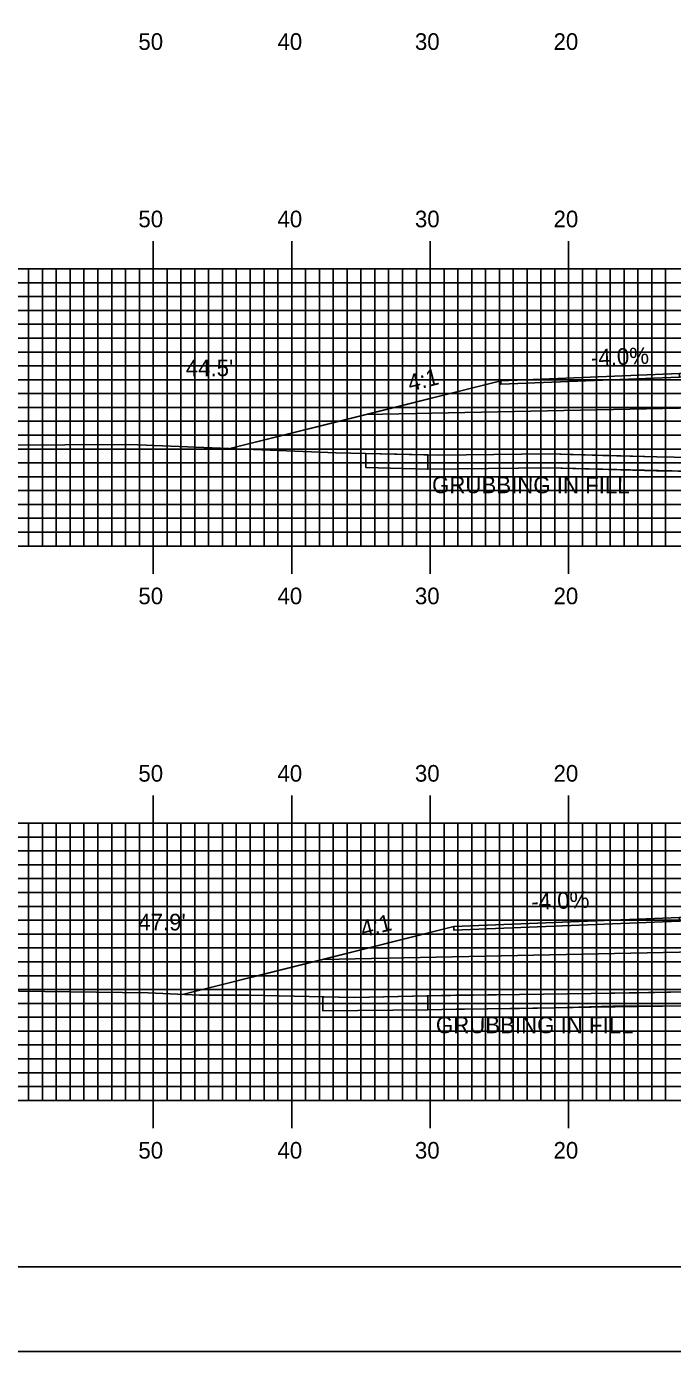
# Model space of a CAD drawing. Extents: x 1773990 to 1774333, y 442591 to 442811.
# Drawn here: x 1774096.5 to 1774143.2, y 442590.5 to 442686.2 of the extents above; entities that cross this region are included whole.
import ezdxf

# ---------------------------------------------------------------- set-up
doc = ezdxf.new("R2010")
doc.units = 0
for name, color, linetype in [('ANNOTATION', 7, 'Continuous'), ('BORDER', 7, 'Continuous'), ('D_Roadway_Centerline', 7, 'Continuous'), ('D_Roadway_Edge_Shoulder', 7, 'Continuous'), ('D_Roadway_SlopeLines', 7, 'Continuous'), ('D_Roadway_SubGrade', 7, 'Continuous'), ('D_Text_Standard', 7, 'Continuous'), ('GRUBBING IN FILL', 7, 'Continuous'), ('H_V ANNOTATION', 7, 'Continuous'), ('MAJOR', 7, 'Continuous'), ('MINOR', 7, 'Continuous'), ('PLOT BOUNDARY', 7, 'Continuous'), ('S_Roadway_Centerline', 7, 'Continuous')]:
    doc.layers.add(name, color=color, linetype=linetype)

msp = doc.modelspace()

# ---------------------------------------------------------------- linework, layer by layer
at = {"layer": 'BORDER'}
msp.add_lwpolyline([(1774006.059, 442596.665), (1774326.059, 442596.665), (1774326.059, 442806.665), (1774006.059, 442806.665)], close=True, dxfattribs=at)
at = {"layer": 'D_Roadway_Centerline'}
for points in [[(1774111.186, 442655.695), (1774121.01, 442658.151), (1774130.759, 442660.588), (1774143.659, 442661.104), (1774143.66, 442661.104), (1774152.062, 442661.272), (1774155.659, 442661.344), (1774167.659, 442661.104), (1774170.226, 442661.002), (1774175.659, 442660.784), (1774184.924, 442658.468), (1774185.833, 442658.24), (1774201.809, 442654.246), (1774201.81, 442654.246)], [(1774107.784, 442616.308), (1774117.905, 442618.838), (1774127.359, 442621.202), (1774143.659, 442621.854), (1774155.659, 442622.094), (1774161.174, 442621.984), (1774167.659, 442621.854), (1774171.953, 442621.682), (1774175.659, 442621.534), (1774185.833, 442618.99), (1774199.367, 442615.606)]]:
    msp.add_lwpolyline(points, dxfattribs=at)
at = {"layer": 'D_Roadway_Edge_Shoulder'}
for points in [[(1774143.659, 442661.104), (1774130.759, 442660.588), (1774130.759, 442660.338), (1774143.659, 442660.854)], [(1774143.659, 442621.854), (1774127.359, 442621.202), (1774127.359, 442620.952), (1774143.659, 442621.604)]]:
    msp.add_lwpolyline(points, close=True, dxfattribs=at)
at = {"layer": 'D_Roadway_SlopeLines'}
for points in [[(1774130.759, 442660.588), (1774120.585, 442658.044), (1774118.76, 442657.588), (1774111.186, 442655.695)], [(1774127.359, 442621.202), (1774117.185, 442618.658), (1774115.358, 442618.202), (1774107.784, 442616.308)]]:
    msp.add_lwpolyline(points, dxfattribs=at)
at = {"layer": 'D_Roadway_SubGrade'}
for points in [[(1774143.659, 442658.604), (1774121.01, 442658.151), (1774130.759, 442660.588), (1774130.759, 442660.338), (1774143.659, 442660.854), (1774155.659, 442661.094), (1774167.659, 442660.854), (1774175.659, 442660.534), (1774175.659, 442660.784), (1774185.833, 442658.24), (1774167.659, 442658.604), (1774155.659, 442658.844)], [(1774143.659, 442619.354), (1774117.905, 442618.838), (1774127.359, 442621.202), (1774127.359, 442620.952), (1774143.659, 442621.604), (1774155.659, 442621.844), (1774167.659, 442621.604), (1774175.659, 442621.284), (1774175.659, 442621.534), (1774185.833, 442618.99), (1774167.659, 442619.354), (1774155.659, 442619.594)]]:
    msp.add_lwpolyline(points, close=True, dxfattribs=at)
at = {"layer": 'GRUBBING IN FILL'}
for p, q in [((1774125.485, 442655.237), (1774121.01, 442655.333)), ((1774125.485, 442655.237), (1774125.485, 442654.211)), ((1774125.485, 442654.211), (1774125.485, 442655.237)), ((1774120.185, 442616.092), (1774117.905, 442616.138)), ((1774125.485, 442616.21), (1774120.185, 442616.092)), ((1774125.485, 442616.21), (1774125.485, 442615.21)), ((1774125.485, 442615.21), (1774125.485, 442616.21))]:
    msp.add_line(p, q, dxfattribs=at)
for points in [[(1774121.01, 442655.333), (1774121.01, 442654.333), (1774125.485, 442654.211)], [(1774121.01, 442655.333), (1774121.01, 442654.333), (1774125.485, 442654.211)], [(1774125.485, 442654.211), (1774134.235, 442654.315), (1774138.123, 442654.206), (1774145.135, 442654.046), (1774148.26, 442653.994), (1774152.504, 442653.952), (1774155.659, 442653.921), (1774155.659, 442654.921), (1774152.509, 442654.952), (1774148.273, 442654.994), (1774142.032, 442655.097), (1774138.138, 442655.206), (1774134.243, 442655.315), (1774130.25, 442655.268), (1774126.257, 442655.22), (1774125.485, 442655.237)], [(1774125.485, 442654.211), (1774134.235, 442654.315), (1774142.01, 442654.097), (1774148.26, 442653.994), (1774156.748, 442653.91), (1774168.548, 442654.069), (1774170.602, 442654.088), (1774172.142, 442654.082), (1774185.833, 442653.644)], [(1774125.485, 442654.211), (1774134.235, 442654.315), (1774142.01, 442654.097), (1774148.26, 442653.994), (1774156.748, 442653.91), (1774168.548, 442654.069), (1774170.602, 442654.088), (1774172.142, 442654.082), (1774185.833, 442653.644)], [(1774125.485, 442616.21), (1774132.101, 442616.307), (1774140.725, 442616.436), (1774144.174, 442616.491), (1774150.849, 442616.51), (1774155.659, 442616.523), (1774155.659, 442615.522), (1774150.852, 442615.51), (1774147.518, 442615.5), (1774144.183, 442615.491), (1774138.846, 442615.476), (1774134.703, 442615.344), (1774126.507, 442615.233), (1774125.485, 442615.21)], [(1774117.905, 442616.138), (1774117.905, 442615.138), (1774125.485, 442615.21)], [(1774117.905, 442616.138), (1774117.905, 442615.138), (1774125.485, 442615.21)], [(1774125.485, 442615.21), (1774127.529, 442615.255), (1774132.114, 442615.307), (1774137.292, 442615.382), (1774144.183, 442615.491), (1774150.852, 442615.51), (1774155.673, 442615.522), (1774160.779, 442615.365), (1774178.086, 442614.715), (1774185.833, 442614.569)], [(1774125.485, 442615.21), (1774127.529, 442615.255), (1774132.114, 442615.307), (1774137.292, 442615.382), (1774144.183, 442615.491), (1774150.852, 442615.51), (1774155.673, 442615.522), (1774160.779, 442615.365), (1774178.086, 442614.715), (1774185.833, 442614.569)]]:
    msp.add_lwpolyline(points, dxfattribs=at)
for points in [[(1774125.485, 442655.237), (1774125.485, 442654.211), (1774134.235, 442654.315), (1774138.123, 442654.206), (1774145.135, 442654.046), (1774148.26, 442653.994), (1774152.504, 442653.952), (1774155.659, 442653.921), (1774155.659, 442654.921), (1774152.509, 442654.952), (1774148.273, 442654.994), (1774142.032, 442655.097), (1774138.138, 442655.206), (1774134.243, 442655.315), (1774130.25, 442655.268), (1774126.257, 442655.22)], [(1774125.485, 442616.21), (1774132.101, 442616.307), (1774140.725, 442616.436), (1774144.174, 442616.491), (1774150.849, 442616.51), (1774155.659, 442616.523), (1774155.659, 442615.522), (1774150.852, 442615.51), (1774147.518, 442615.5), (1774144.183, 442615.491), (1774138.846, 442615.476), (1774134.703, 442615.344), (1774126.507, 442615.233), (1774125.485, 442615.21)]]:
    msp.add_lwpolyline(points, close=True, dxfattribs=at)
at = {"layer": 'MAJOR'}
for p, q in [((1774105.659, 442670.669), (1774105.659, 442668.665)), ((1774115.659, 442670.669), (1774115.659, 442668.665)), ((1774125.659, 442670.669), (1774125.659, 442668.665)), ((1774135.659, 442670.669), (1774135.659, 442668.665)), ((1774015.659, 442668.665), (1774295.659, 442668.665)), ((1774015.659, 442668.665), (1774295.659, 442668.665)), ((1774105.659, 442648.665), (1774105.659, 442668.665)), ((1774115.659, 442648.665), (1774115.659, 442668.665)), ((1774125.659, 442648.665), (1774125.659, 442668.665)), ((1774135.659, 442648.665), (1774135.659, 442668.665)), ((1774015.659, 442663.665), (1774295.659, 442663.665)), ((1774015.659, 442658.665), (1774295.659, 442658.665)), ((1774015.659, 442653.665), (1774295.659, 442653.665)), ((1774015.659, 442648.665), (1774295.659, 442648.665)), ((1774015.659, 442648.665), (1774295.659, 442648.665)), ((1774105.659, 442646.661), (1774105.659, 442648.665)), ((1774115.659, 442646.661), (1774115.659, 442648.665)), ((1774125.659, 442646.661), (1774125.659, 442648.665)), ((1774135.659, 442646.661), (1774135.659, 442648.665)), ((1774105.659, 442630.669), (1774105.659, 442628.665)), ((1774115.659, 442630.669), (1774115.659, 442628.665)), ((1774125.659, 442630.669), (1774125.659, 442628.665)), ((1774135.659, 442630.669), (1774135.659, 442628.665)), ((1774015.659, 442628.665), (1774295.659, 442628.665)), ((1774015.659, 442628.665), (1774295.659, 442628.665)), ((1774105.659, 442608.665), (1774105.659, 442628.665)), ((1774115.659, 442608.665), (1774115.659, 442628.665)), ((1774125.659, 442608.665), (1774125.659, 442628.665)), ((1774135.659, 442608.665), (1774135.659, 442628.665)), ((1774015.659, 442623.665), (1774295.659, 442623.665)), ((1774015.659, 442618.665), (1774295.659, 442618.665)), ((1774015.659, 442613.665), (1774295.659, 442613.665)), ((1774015.659, 442608.665), (1774295.659, 442608.665)), ((1774015.659, 442608.665), (1774295.659, 442608.665)), ((1774105.659, 442606.661), (1774105.659, 442608.665)), ((1774115.659, 442606.661), (1774115.659, 442608.665)), ((1774125.659, 442606.661), (1774125.659, 442608.665)), ((1774135.659, 442606.661), (1774135.659, 442608.665))]:
    msp.add_line(p, q, dxfattribs=at)
at = {"layer": 'MINOR'}
for p, q in [((1774096.659, 442648.665), (1774096.659, 442668.665)), ((1774097.659, 442648.665), (1774097.659, 442668.665)), ((1774098.659, 442648.665), (1774098.659, 442668.665)), ((1774099.659, 442648.665), (1774099.659, 442668.665)), ((1774100.659, 442648.665), (1774100.659, 442668.665)), ((1774101.659, 442648.665), (1774101.659, 442668.665)), ((1774102.659, 442648.665), (1774102.659, 442668.665)), ((1774103.659, 442648.665), (1774103.659, 442668.665)), ((1774104.659, 442648.665), (1774104.659, 442668.665)), ((1774106.659, 442648.665), (1774106.659, 442668.665)), ((1774107.659, 442648.665), (1774107.659, 442668.665)), ((1774108.659, 442648.665), (1774108.659, 442668.665)), ((1774109.659, 442648.665), (1774109.659, 442668.665)), ((1774110.659, 442648.665), (1774110.659, 442668.665)), ((1774111.659, 442648.665), (1774111.659, 442668.665)), ((1774112.659, 442648.665), (1774112.659, 442668.665)), ((1774113.659, 442648.665), (1774113.659, 442668.665)), ((1774114.659, 442648.665), (1774114.659, 442668.665)), ((1774116.659, 442648.665), (1774116.659, 442668.665)), ((1774117.659, 442648.665), (1774117.659, 442668.665)), ((1774118.659, 442648.665), (1774118.659, 442668.665)), ((1774119.659, 442648.665), (1774119.659, 442668.665)), ((1774120.659, 442648.665), (1774120.659, 442668.665)), ((1774121.659, 442648.665), (1774121.659, 442668.665)), ((1774122.659, 442648.665), (1774122.659, 442668.665)), ((1774123.659, 442648.665), (1774123.659, 442668.665)), ((1774124.659, 442648.665), (1774124.659, 442668.665)), ((1774126.659, 442648.665), (1774126.659, 442668.665)), ((1774127.659, 442648.665), (1774127.659, 442668.665)), ((1774128.659, 442648.665), (1774128.659, 442668.665)), ((1774129.659, 442648.665), (1774129.659, 442668.665)), ((1774130.659, 442648.665), (1774130.659, 442668.665)), ((1774131.659, 442648.665), (1774131.659, 442668.665)), ((1774132.659, 442648.665), (1774132.659, 442668.665)), ((1774133.659, 442648.665), (1774133.659, 442668.665)), ((1774134.659, 442648.665), (1774134.659, 442668.665)), ((1774136.659, 442648.665), (1774136.659, 442668.665)), ((1774137.659, 442648.665), (1774137.659, 442668.665)), ((1774138.659, 442648.665), (1774138.659, 442668.665)), ((1774139.659, 442648.665), (1774139.659, 442668.665)), ((1774140.659, 442648.665), (1774140.659, 442668.665)), ((1774141.659, 442648.665), (1774141.659, 442668.665)), ((1774142.659, 442648.665), (1774142.659, 442668.665)), ((1774015.659, 442667.665), (1774295.659, 442667.665)), ((1774015.659, 442666.665), (1774295.659, 442666.665)), ((1774015.659, 442665.665), (1774295.659, 442665.665)), ((1774015.659, 442664.665), (1774295.659, 442664.665)), ((1774015.659, 442662.665), (1774295.659, 442662.665)), ((1774015.659, 442661.665), (1774295.659, 442661.665)), ((1774015.659, 442660.665), (1774295.659, 442660.665)), ((1774015.659, 442659.665), (1774295.659, 442659.665)), ((1774015.659, 442657.665), (1774295.659, 442657.665)), ((1774015.659, 442656.665), (1774295.659, 442656.665)), ((1774015.659, 442655.665), (1774295.659, 442655.665)), ((1774015.659, 442654.665), (1774295.659, 442654.665)), ((1774015.659, 442652.665), (1774295.659, 442652.665)), ((1774015.659, 442651.665), (1774295.659, 442651.665)), ((1774015.659, 442650.665), (1774295.659, 442650.665)), ((1774015.659, 442649.665), (1774295.659, 442649.665)), ((1774096.659, 442608.665), (1774096.659, 442628.665)), ((1774097.659, 442608.665), (1774097.659, 442628.665)), ((1774098.659, 442608.665), (1774098.659, 442628.665)), ((1774099.659, 442608.665), (1774099.659, 442628.665)), ((1774100.659, 442608.665), (1774100.659, 442628.665)), ((1774101.659, 442608.665), (1774101.659, 442628.665)), ((1774102.659, 442608.665), (1774102.659, 442628.665)), ((1774103.659, 442608.665), (1774103.659, 442628.665)), ((1774104.659, 442608.665), (1774104.659, 442628.665)), ((1774106.659, 442608.665), (1774106.659, 442628.665)), ((1774107.659, 442608.665), (1774107.659, 442628.665)), ((1774108.659, 442608.665), (1774108.659, 442628.665)), ((1774109.659, 442608.665), (1774109.659, 442628.665)), ((1774110.659, 442608.665), (1774110.659, 442628.665)), ((1774111.659, 442608.665), (1774111.659, 442628.665)), ((1774112.659, 442608.665), (1774112.659, 442628.665)), ((1774113.659, 442608.665), (1774113.659, 442628.665)), ((1774114.659, 442608.665), (1774114.659, 442628.665)), ((1774116.659, 442608.665), (1774116.659, 442628.665)), ((1774117.659, 442608.665), (1774117.659, 442628.665)), ((1774118.659, 442608.665), (1774118.659, 442628.665)), ((1774119.659, 442608.665), (1774119.659, 442628.665)), ((1774120.659, 442608.665), (1774120.659, 442628.665)), ((1774121.659, 442608.665), (1774121.659, 442628.665)), ((1774122.659, 442608.665), (1774122.659, 442628.665)), ((1774123.659, 442608.665), (1774123.659, 442628.665)), ((1774124.659, 442608.665), (1774124.659, 442628.665)), ((1774126.659, 442608.665), (1774126.659, 442628.665)), ((1774127.659, 442608.665), (1774127.659, 442628.665)), ((1774128.659, 442608.665), (1774128.659, 442628.665)), ((1774129.659, 442608.665), (1774129.659, 442628.665)), ((1774130.659, 442608.665), (1774130.659, 442628.665)), ((1774131.659, 442608.665), (1774131.659, 442628.665)), ((1774132.659, 442608.665), (1774132.659, 442628.665)), ((1774133.659, 442608.665), (1774133.659, 442628.665)), ((1774134.659, 442608.665), (1774134.659, 442628.665)), ((1774136.659, 442608.665), (1774136.659, 442628.665)), ((1774137.659, 442608.665), (1774137.659, 442628.665)), ((1774138.659, 442608.665), (1774138.659, 442628.665)), ((1774139.659, 442608.665), (1774139.659, 442628.665)), ((1774140.659, 442608.665), (1774140.659, 442628.665)), ((1774141.659, 442608.665), (1774141.659, 442628.665)), ((1774142.659, 442608.665), (1774142.659, 442628.665)), ((1774015.659, 442627.665), (1774295.659, 442627.665)), ((1774015.659, 442626.665), (1774295.659, 442626.665)), ((1774015.659, 442625.665), (1774295.659, 442625.665)), ((1774015.659, 442624.665), (1774295.659, 442624.665)), ((1774015.659, 442622.665), (1774295.659, 442622.665)), ((1774015.659, 442621.665), (1774295.659, 442621.665)), ((1774015.659, 442620.665), (1774295.659, 442620.665)), ((1774015.659, 442619.665), (1774295.659, 442619.665)), ((1774015.659, 442617.665), (1774295.659, 442617.665)), ((1774015.659, 442616.665), (1774295.659, 442616.665)), ((1774015.659, 442615.665), (1774295.659, 442615.665)), ((1774015.659, 442614.665), (1774295.659, 442614.665)), ((1774015.659, 442612.665), (1774295.659, 442612.665)), ((1774015.659, 442611.665), (1774295.659, 442611.665)), ((1774015.659, 442610.665), (1774295.659, 442610.665)), ((1774015.659, 442609.665), (1774295.659, 442609.665))]:
    msp.add_line(p, q, dxfattribs=at)
at = {"layer": 'PLOT BOUNDARY'}
msp.add_lwpolyline([(1773989.872, 442590.547), (1774329.872, 442590.547), (1774329.872, 442810.547), (1773989.872, 442810.547)], close=True, dxfattribs=at)
at = {"layer": 'S_Roadway_Centerline'}
for points in [[(1774015.659, 442657.229), (1774029.156, 442656.948), (1774037.11, 442656.928), (1774041.73, 442656.856), (1774046.169, 442656.612), (1774058.455, 442656.465), (1774070.608, 442656.245), (1774076.731, 442656.201), (1774082.317, 442655.875), (1774094.599, 442655.94), (1774103.95, 442655.992), (1774118.873, 442655.379), (1774126.257, 442655.22), (1774134.243, 442655.315), (1774142.032, 442655.097), (1774148.273, 442654.994), (1774156.746, 442654.91), (1774168.537, 442655.069), (1774170.6, 442655.088), (1774172.16, 442655.082), (1774191.439, 442654.465), (1774193.508, 442654.378), (1774213.524, 442654.06)], [(1774088.493, 442616.632), (1774105.299, 442616.428), (1774108.99, 442616.25), (1774112.564, 442616.247), (1774120.185, 442616.092), (1774127.512, 442616.255), (1774132.101, 442616.307), (1774137.277, 442616.382), (1774144.174, 442616.491), (1774150.849, 442616.51), (1774155.687, 442616.522), (1774160.813, 442616.364), (1774178.114, 442615.715), (1774185.703, 442615.571), (1774194.728, 442615.518), (1774210.121, 442615.813)]]:
    msp.add_lwpolyline(points, dxfattribs=at)

# ---------------------------------------------------------------- texts
at = {"layer": 'ANNOTATION'}
for s, rotation, p in [('-4.0%', 2.29054, (1774137.291, 442661.651)), ('4:1', 14.03855, (1774124.207, 442659.812)), ('-4.0%', 2.29084, (1774132.982, 442622.401)), ('4:1', 14.03844, (1774120.807, 442620.426))]:
    msp.add_text(s, height=1.2, rotation=rotation, dxfattribs=at).set_placement(p)
at = {"layer": 'D_Text_Standard'}
for s, p in [("44.5'", (1774108.008, 442660.921)), ("47.9'", (1774104.578, 442620.931))]:
    msp.add_text(s, height=1.2, dxfattribs=at).set_placement(p)
at = {"layer": 'GRUBBING IN FILL'}
for rotation, p in [(359.93557, (1774125.794, 442652.482)), (359.97468, (1774126.071, 442613.514))]:
    msp.add_text('GRUBBING IN FILL', height=1.2, rotation=rotation, dxfattribs=at).set_placement(p)
at = {"layer": 'H_V ANNOTATION'}
for s, p in [('50', (1774104.588, 442684.465)), ('40', (1774114.631, 442684.465)), ('30', (1774124.556, 442684.465)), ('20', (1774134.567, 442684.465)), ('50', (1774104.588, 442671.665)), ('40', (1774114.631, 442671.665)), ('30', (1774124.556, 442671.665)), ('20', (1774134.567, 442671.665)), ('50', (1774104.588, 442644.465)), ('40', (1774114.631, 442644.465)), ('30', (1774124.556, 442644.465)), ('20', (1774134.567, 442644.465)), ('50', (1774104.588, 442631.665)), ('40', (1774114.631, 442631.665)), ('30', (1774124.556, 442631.665)), ('20', (1774134.567, 442631.665)), ('50', (1774104.588, 442604.465)), ('40', (1774114.631, 442604.465)), ('30', (1774124.556, 442604.465)), ('20', (1774134.567, 442604.465))]:
    msp.add_text(s, height=1.2, dxfattribs=at).set_placement(p)

doc.saveas('drawing.dxf')
